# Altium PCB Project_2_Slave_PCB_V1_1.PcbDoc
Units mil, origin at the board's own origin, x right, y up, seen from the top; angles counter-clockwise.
Board outline 3444 x 3925 mil, 2 copper layers (Top Layer, Bottom Layer); 82 components, 95 nets, 252 pads, 68 vias.
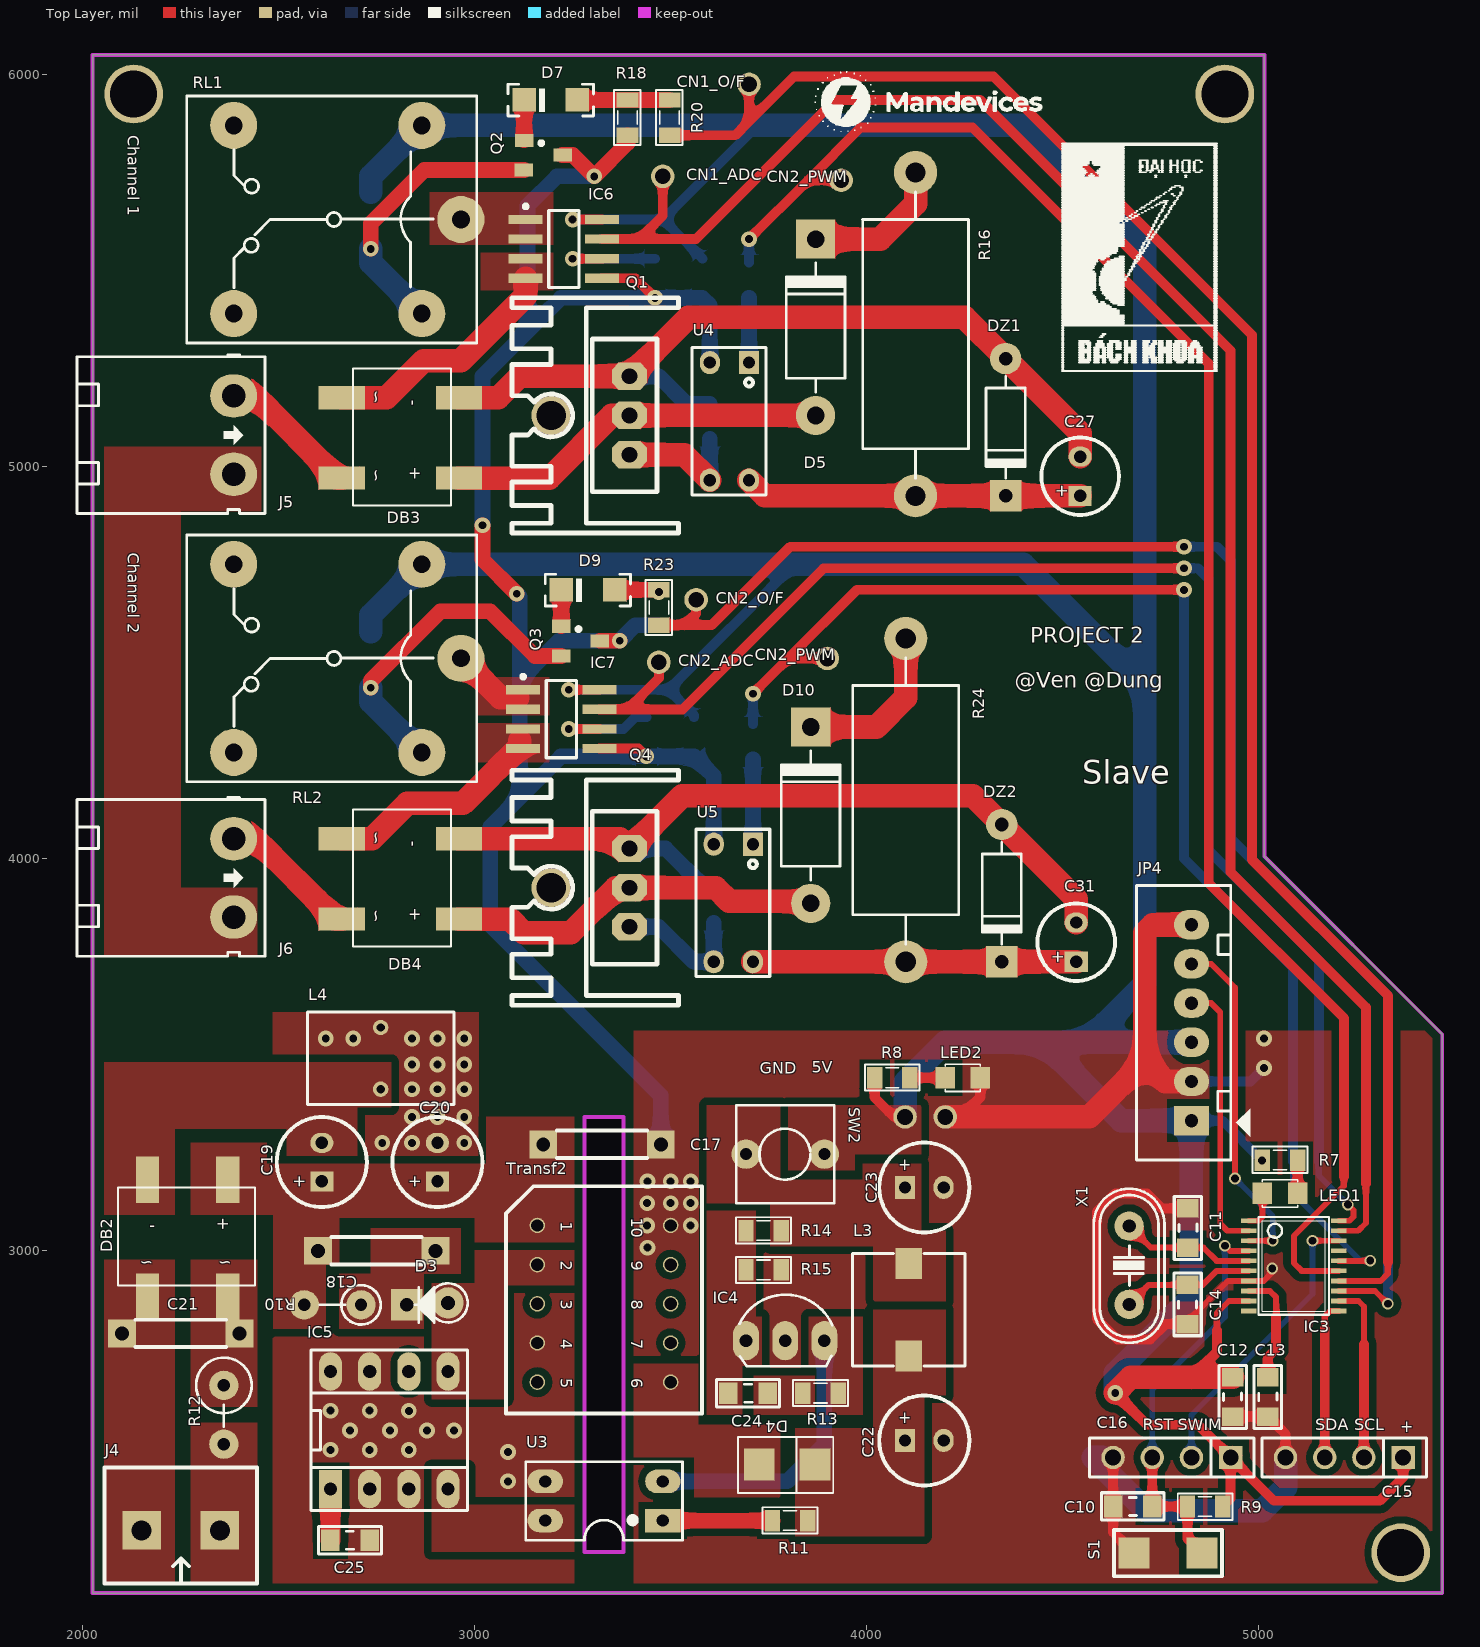
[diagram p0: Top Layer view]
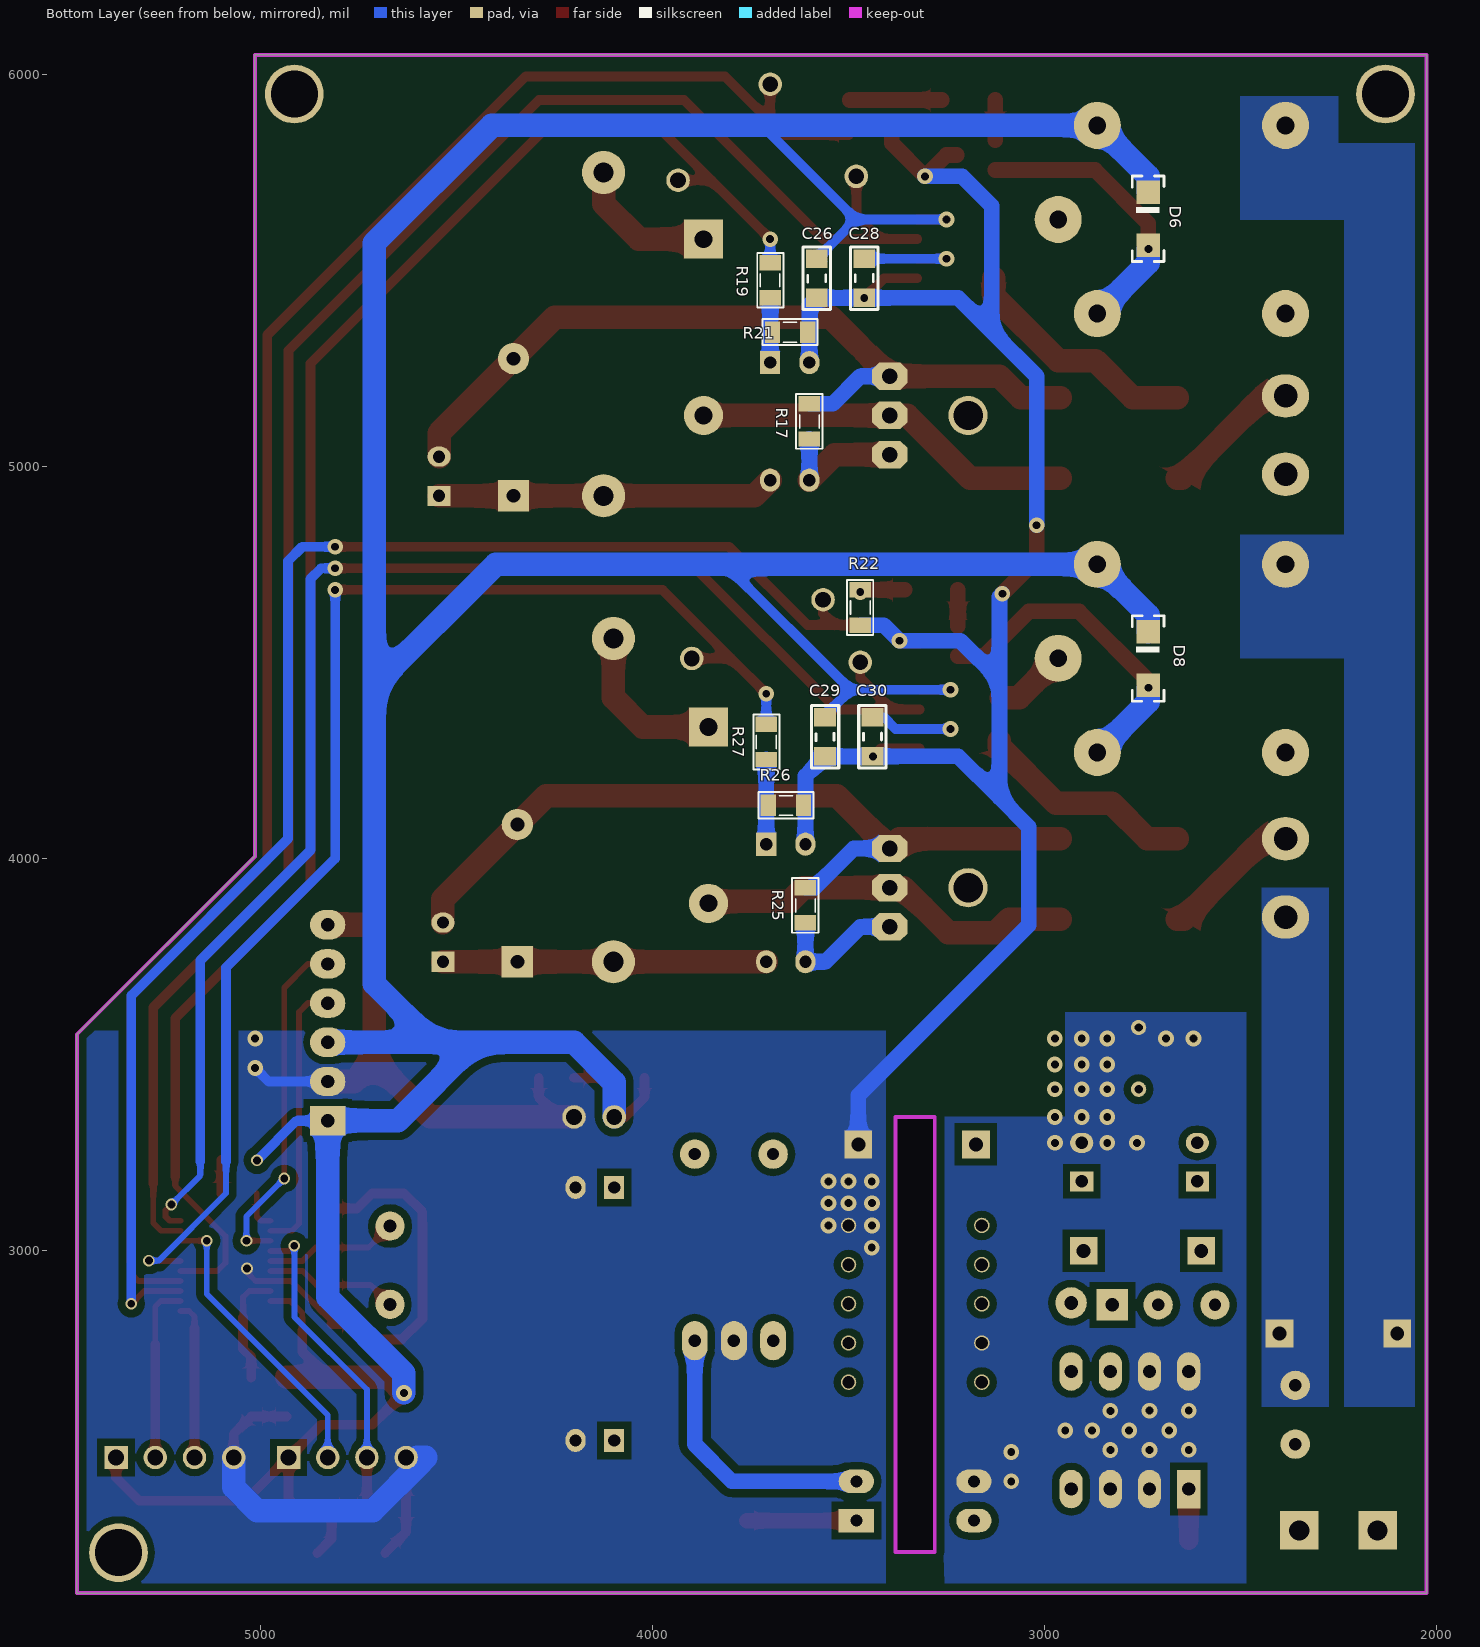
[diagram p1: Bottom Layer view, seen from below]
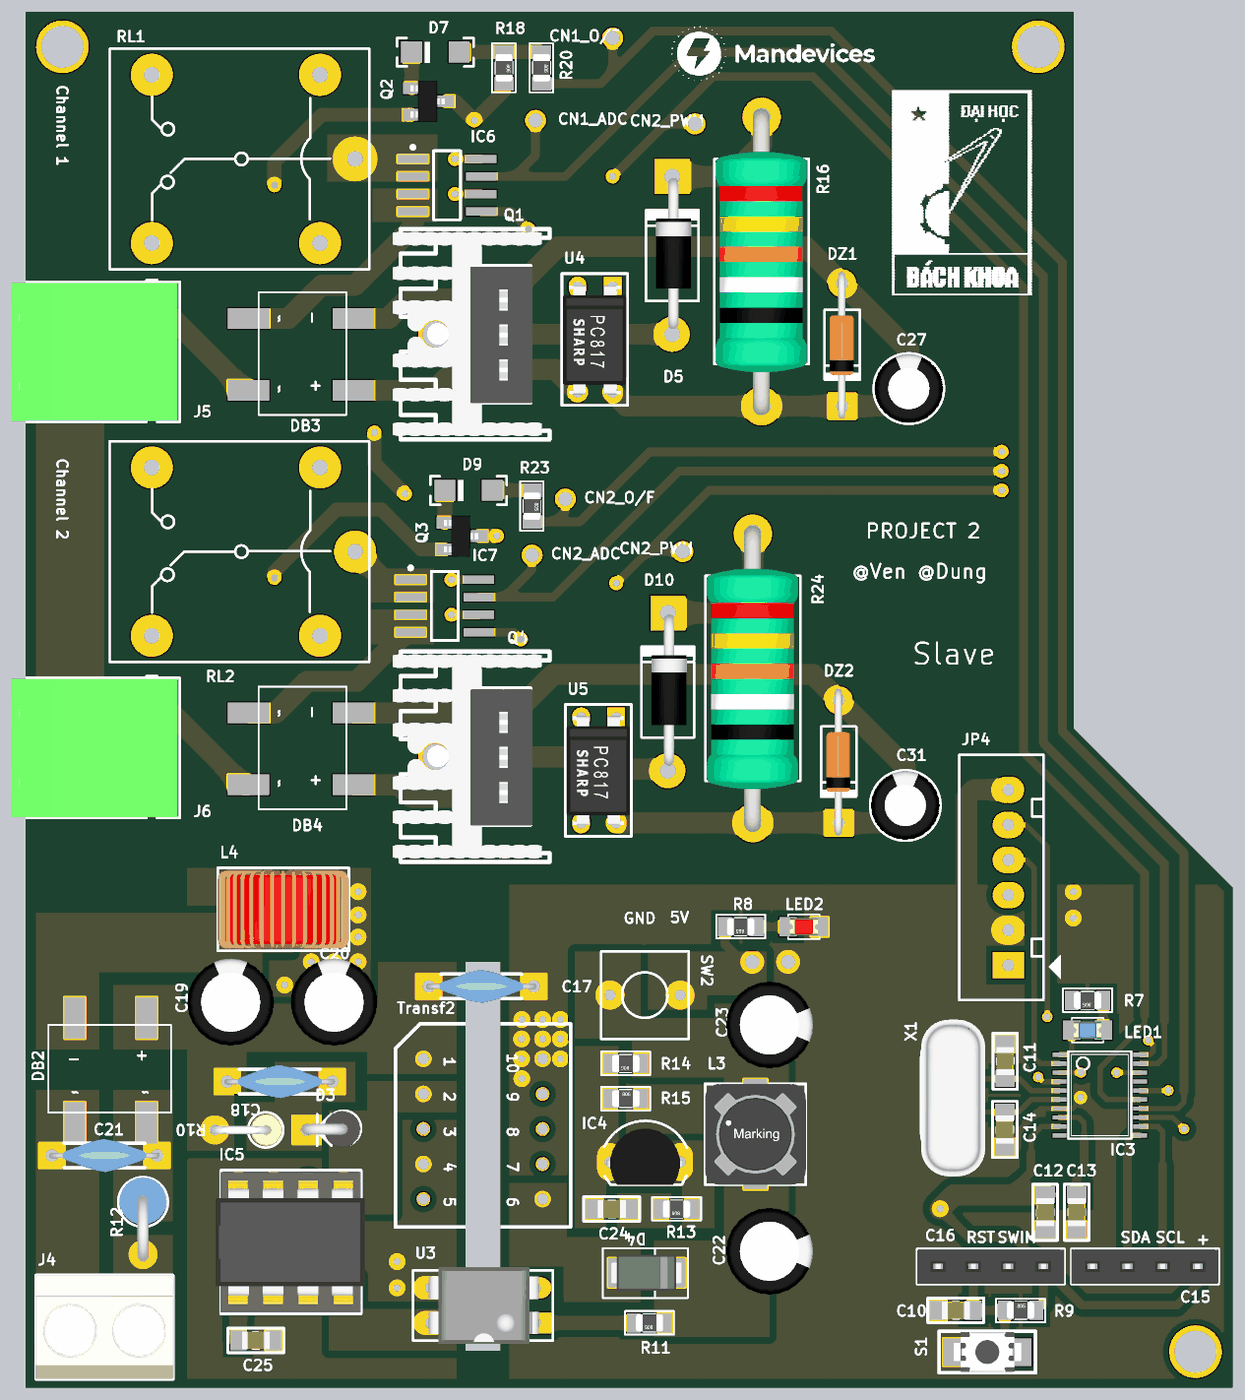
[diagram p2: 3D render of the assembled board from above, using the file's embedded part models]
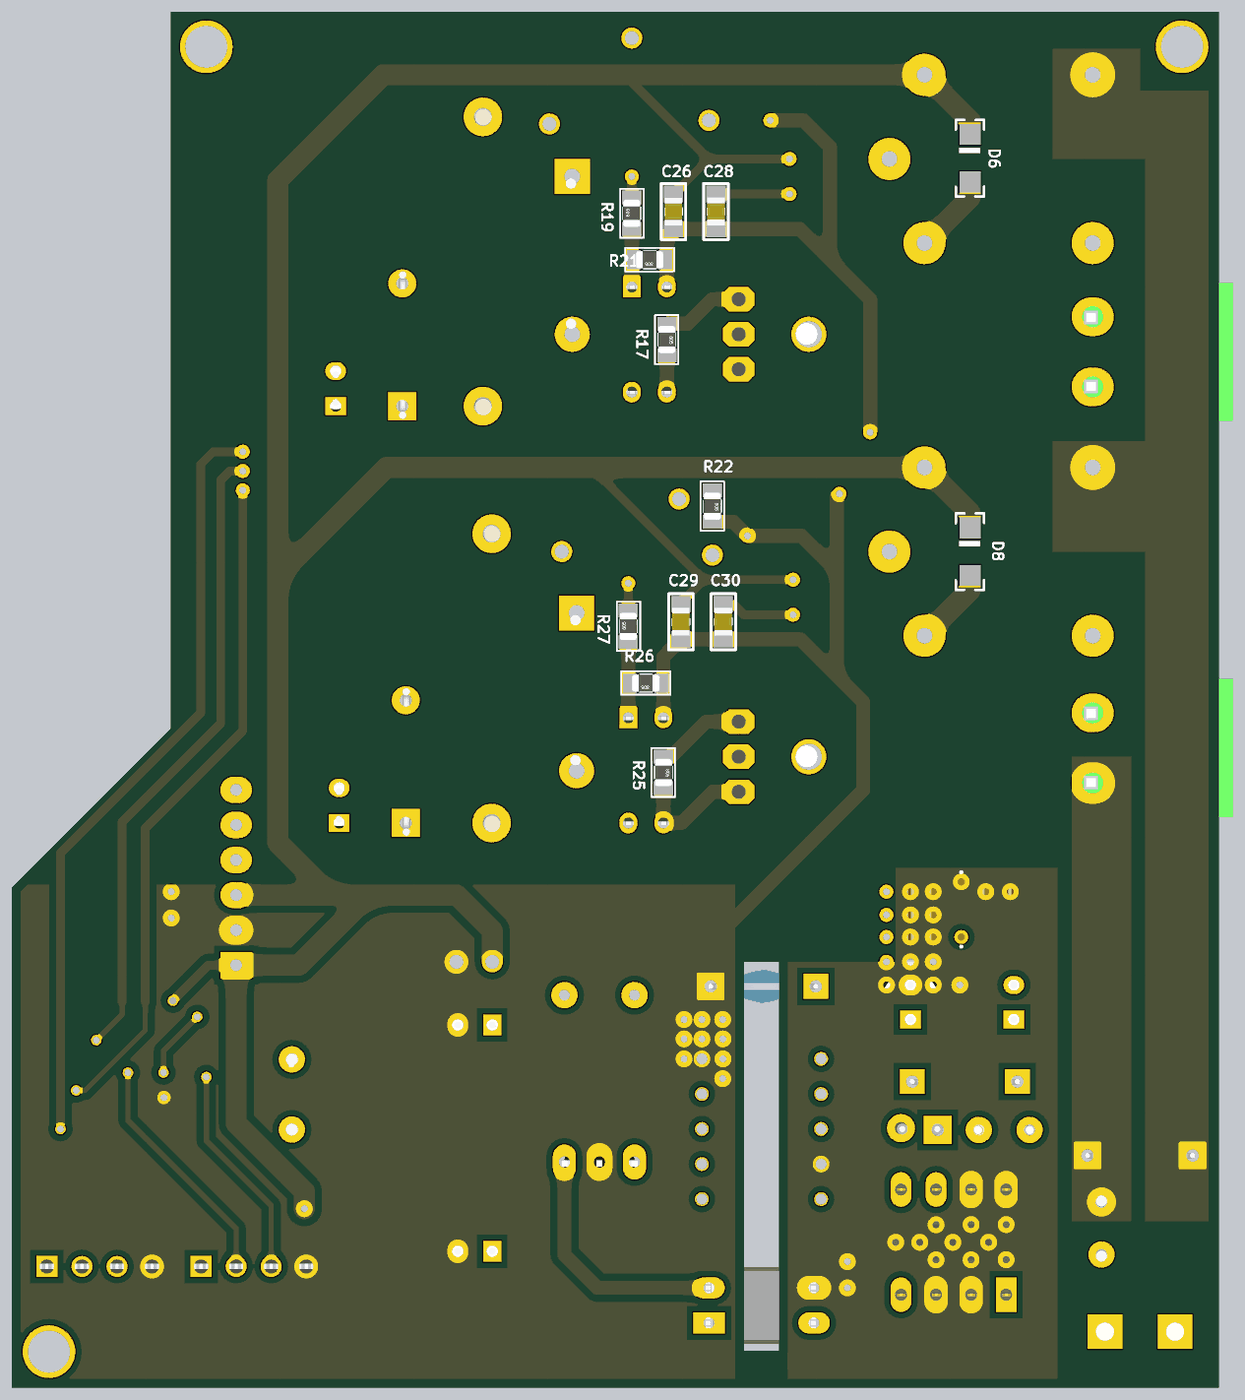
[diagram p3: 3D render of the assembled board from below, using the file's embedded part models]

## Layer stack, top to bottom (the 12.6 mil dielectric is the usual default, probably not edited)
Top Solder: solder mask 0.4, Solder Resist, Dk 3.5
Top Layer: signal copper 1.4
Dielectric 1: dielectric 12.6, FR-4, Dk 4.8
Bottom Layer: signal copper 1.4
Bottom Solder: solder mask 0.4, Solder Resist, Dk 3.5

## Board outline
2025,2125 2025,6050 5015,6050 5015,4005 5469,3551 5469,2125
cut-out: 3280,2230 3380,2230 3380,3340 3280,3340

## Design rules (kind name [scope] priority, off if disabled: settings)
Clearance [All] p1: gap=20 ignorepadtopadclearanceinfootprint=TRUE except(0: Arc-Text Arc-Hole Track-Text Track-Hole SMDPad-Text SMDPad-Hole THPad-Text THPad-Hole Via-Text Via-Hole Fill-Text Fill-Hole Poly-Text Poly-Hole Region-Text Region-Hole Text-Text Text-Hole; 10: Arc-Arc Arc-Track Arc-SMDPad Arc-THPad Arc-Via Track-Track Track-SMDPad Track-THPad Track-Via SMDPad-SMDPad SMDPad-THPad SMDPad-Via THPad-THPad THPad-Via Via-Via; 18: THPad-Fill THPad-Poly THPad-Region)
PolygonConnect [All] p1: connectstyle=Direct reliefconductorwidth=10 reliefentries=4 polygonreliefangle="90 Angle" airgapwidth=10
RoutingVias [All] p1: holewidth=20 width=40 viastyle="Through Hole" minholewidth=15 minwidth=25 maxholewidth=25 maxwidth=45
SolderMaskExpansion [All] p1: expansion=4
Width [All] p1: maxlimit=60 minlimit=15 preferedwidth=25
30 further rules are at their usual default settings.

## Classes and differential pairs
component class 8: JP4
component class 7: C26 C27 C28 C29 C30 C31 D5 D6 D7 D8 D9 D10 DB3 DB4 DZ1 DZ2 IC6 IC7 J5 J6 Q1 Q2 Q3 Q4 R16 R17 R19 R20 R23 R24 R25 R26 R27 RL1 RL2 U4 U5
component class 6: C17 C18 C19 C20 C21 C22 C23 C24 C25 D3 D4 DB2 IC4 IC5 J4 L3 R10 R11 R12 R13 R14 R15 SW2 Transf2 U3
component class 5: C10 C11 C12 C13 C14 C15 C16 IC3 LED1 LED2 R7 R8 R9 S1 X1

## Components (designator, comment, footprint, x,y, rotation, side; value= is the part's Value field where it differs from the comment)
C10 "1uF" CAP_0805 4679,2347 r0 top value=33p
C11 "22pF" CAP_0805 4819,3056.61 r90 top value=33p
C12 "100nF" CAP_0805 4933,2625.5 r90 top value=33p
C13 "1uF" CAP_0805 5023,2625.5 r90 top value=33p
C14 "22pF" CAP_0805 4820,2861.61 r270 top value=33p
C15 "JP4" JP4-C1T 5369,2471 r180 top
C16 "JP4" JP4-C1T 4929,2471 r180 top
C17 "1nF/400v" 103/2KV 3475.04,3270 r180 top
C18 "1nF/400V" 103/2KV 2600,2998.34 r0 top
C19 "6.8uF/400V" C8mm 2610,3224.71 r90 top
C20 "6.8uF/400V" C8mm 2905,3224.71 r90 top
C21 "20D471K" 103/2KV 2100,2787.5 r0 top
C22 "1000uF/16V" C8mm 4147.38,2514.45 r0 top
C23 "470uF/16V" C8mm 4147.38,3160 r0 top
C24 "100nF" CAP_0805 3697.38,2636 r0 top value=33p
C25 "100nF" CAP_0805 2681.99,2259 r180 top value=33p
C26 "100nF" CAP_0805 3580,5480 r270 bottom value=33p
C27 "Cap Pol" C5mm 4545,4975 r90 top
C28 "10nF" CAP_0805 3461,5480 r90 bottom value=33p
C29 "100nF" CAP_0805 3559,4310 r270 bottom value=33p
C30 "10nF" CAP_0805 3440,4310 r90 bottom value=33p
C31 "Cap Pol" C5mm 4535,3786 r90 top
D3 "1N4937" DIO-1AN 2876.99,2860.5 r0 top value=1N5007
D4 "SS14" DO-214AC(SMA) 3775,2450 r180 top value=1N5007
D5 "1N4007" D2A 3870,5580 r270 top
D6 "1N4148" 1N4148_SMD 2735,5632.09 r90 bottom value="Diode c?m 1N5408"
D7 "1N4148" 1N4148_SMD 3193.91,5935 r180 top value="Diode c?m 1N5408"
D8 "1N4148" 1N4148_SMD 2735,4510 r90 bottom value="Diode c?m 1N5408"
D9 "1N4148" 1N4148_SMD 3288.91,4685 r180 top value="Diode c?m 1N5408"
D10 "1N4007" D2A 3857.5,4335 r270 top
DB2 "Diode Bridge" DB207S 2270,3030 r0 top
DB3 "Diode Bridge Flate" DB207S 2810,5070 r270 top
DB4 "Diode Bridge Flate" DB207S 2810,3945 r270 top
DZ1 "Zener-12V" D1A 4355,5275 r90 top
DZ2 "Zener-12V" D1A 4345,4086 r90 top
IC3 "STM8S003F3P6" TSSOP-20 5090,2960 r270 top value=24Cxx
IC4 "TL431" qto-92 3792.38,2769 r0 top
IC5 "TNY264" DIP8 2780,2540.5 r90 top
IC6 "Current Sensor IC" SOIC-8 3227.44,5555 r0 top
IC7 "Current Sensor IC" SOIC-8 3221,4355 r0 top
J4 "AC-IN" KF2-5.08 2250,2285 r180 top
J5 "LOAD1" KF2-5.08T 2385,5180 r270 top
J6 "LOAD2" KF2-5.08T 2385,4050 r270 top
JP4 "Con6" CON6 4829,3330.42 r90 top value="Connector 6"
L3 "2.2uF" L-SMD-M-7.3x4.5 4107.38,2848.11 r180 top value="150 mH"
L4 "100uF" L-DIP-M-9.5x6 2760,3489.5 r90 top value="150 mH"
LED1 "LED" LED-0805-Blue 5100,3145 r180 top value="LED 3 ly Single Colour"
LED2 "LED" LED-0805-Red 4200.51,3440 r0 top value="LED 3 ly Single Colour"
Q1 "IRF840" QTO-220H3 3395,5030 r90 top
Q2 "2SC1815" SOT23 3175,5795 r270 top value=C1815
Q3 "2SC1815" SOT23 3270,4555 r270 top value=C1815
Q4 "IRF840" QTO-220H3 3395,3825 r90 top
R7 "1k" RES-SMD-0805 5055,3230 r180 top
R8 "1k" RES-SMD-0805 4065.51,3440 r180 top
R9 "10k" RES-SMD-0805 4864,2346 r0 top
R10 "200k" RES-1/4WD 2645,2860.5 r180 top
R11 "200R" RES-SMD-0805 3805,2310 r180 top
R12 "2R" RES-1WD 2360,2590 r270 top
R13 "3.3k" RES-SMD-0805 3882.37,2635 r180 top
R14 "10k" RES-SMD-0805 3737.37,3050 r180 top
R15 "10k" RES-SMD-0805 3737.38,2950 r0 top
R16 "56k/2W" RES-2W 4120,5345 r270 top value="R1/4W - 1K"
R17 "10k" RES-SMD-0805 3600,5115 r270 bottom value="R1/4W - 1K"
R18 "100k" RES-SMD-0805 3390,5890 r270 top
R19 "1k" RES-SMD-0805 3700,5475 r90 bottom
R20 "100R" RES-SMD-0805 3497.25,5890 r270 top
R21 "100k" RES-SMD-0805 3649,5342.31 r0 bottom
R22 "100k" RES-SMD-0805 3470,4640 r270 bottom
R23 "100R" RES-SMD-0805 3470,4640 r270 top
R24 "56k/2W" RES-2W 4095,4156 r270 top value="R1/4W - 1K"
R25 "10k" RES-SMD-0805 3610,3880 r270 bottom value="R1/4W - 1K"
R26 "100k" RES-SMD-0805 3660,4135 r0 bottom
R27 "1k" RES-SMD-0805 3710,4297 r90 bottom
RL1 "Relay 10A/12V" RL_SPDT_10A 2965,5630 r180 top value="Relay SPDT, 10A, 12V"
RL2 "Relay 10A/12V" RL_SPDT_10A 2965,4510 r180 top value="Relay SPDT, 10A, 12V"
S1 "SW-SMD" "SW 3x2x4" 4769,2227 r0 top
SW2 "SW" SW2 3692.38,3245 r0 top value="SW chip 2 pin"
Transf2 "Transformer EE16" "Transformer EE12.7" 3330,2863.18 r270 top
U3 "PC817" DIP4/W0.3 3480,2310 r90 top
U4 "OPTO" OPTO 3700,5264 r270 top value=TLP5211
U5 "OPTO" OPTO 3710,4035 r270 top value=TLP5211
X1 "8Mhz" XT2 4670,2961.61 r90 top value=4Mhz

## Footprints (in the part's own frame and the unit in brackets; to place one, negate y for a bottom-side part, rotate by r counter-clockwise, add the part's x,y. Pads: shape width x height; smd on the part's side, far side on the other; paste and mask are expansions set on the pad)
1N4148_SMD [mil]
  rect 60x60 smd: 1(-67.91,0) 2(67.91,0)
  silkscreen extent -109,-40 109,41, body extent -71,-23 67,25, height 47
103/2KV [mm]
  rect 1.8x1.8 hole 0.9: 1(0,0) 2(7.62,0)
  silkscreen extent 0.89,-0.89 6.73,0.89, body extent -0.19,-1.2 7.81,1.19, height 9.03
C5mm [mm]
  rect 1.3x1.5 hole 0.8: 1(-1.27,0)
  oval 1.3x1.5 hole 0.8: 2(1.27,0)
  silkscreen extent -2.51,-2.51 2.51,2.51, body extent -2.5,-2.5 2.49,2.5, height 11.01
C8mm [mm]
  rect 1.3x1.5 hole 0.8: 1(-1.25,0)
  oval 1.3x1.5 hole 0.8: 2(1.25,0)
  silkscreen extent -2.92,-2.92 2.92,2.92, body extent -3.15,-3.15 3.16,3.15, height 11.51
CAP_0805 [mm]
  rect 1.2x1.4 smd: 1(-1.27,-0.025) 2(1.27,-0.025)
  silkscreen extent -2.03,-0.91 2.03,0.86, body extent -1.01,-0.66 1.01,0.61, height 0.61
CON6 [mil] "CON6"
  rect 75x90 hole 34: 1(0,0)
  oval 75x90 hole 34: 2(100,0) 3(200,0) 4(300,0) 5(400,0) 6(500,0)
  silkscreen extent -100,-150 600,140
D1A [mil] "Diode 1A, W 100mil, L 350mil"
  round 80 hole 35: 1(0,0)
  rect 80x80 hole 35: 2(-350,0)
  silkscreen extent -305,-50 -45,50, body extent -386,-33 34,36, height 84
D2A [mil] "Diode 2A, W 150mil, L 450mil"
  round 100 hole 45: 1(450,0)
  rect 100x100 hole 45: 2(0,0)
  silkscreen extent 61,-75 391,75, body extent 5,-47 435,54, height 100
DB207S [mm] "Bridge Rectifiers 2A 1000V"
  rect 1.5x3 smd: 1(2.54,3.81) 2(2.54,-3.785) 3(-2.667,-3.785) 4(-2.667,3.81)
  silkscreen extent -4.57,-3.05 4.32,3.3
DIO-1AN [mil] "Diode 1A, W 100mil, L 150mil"
  round 80 hole 35: 1(55,5)
  rect 80x80 hole 35: 2(-50,0)
  silkscreen extent -30,-45 105,55, body extent -64,-50 104,55, height 252
DIP4/W0.3 [mil] "4 PIN, W 300mil, Pin to pin 100mil"
  rect 60x90 hole 31: 1(0,0)
  oval 60x90 hole 31: 2(100,0) 3(100,300) 4(0,300)
  silkscreen extent -50,-50 150,350, body extent -59,-10 159,305, height 170
DIP8 [mm]
  rect 2.5x1.5 hole 0.864: 1(-3.81,3.759)
  oval 2.5x1.5 hole 0.864: 2(-3.81,1.219) 3(-3.81,-1.321) 4(-3.81,-3.861) 5(3.81,-3.861) 6(3.81,-1.321) 7(3.81,1.219) 8(3.81,3.759)
  silkscreen extent -5.21,-5.13 5.21,5.03, body extent -5.08,-5.4 5.08,5.4, height 8.1
DO-214AC(SMA) [mm] "DO-214AC Diode Smallest Size"
  rect 2x2.1 smd: 1(1.245,-0.076) 2(-2.367,-0.076)
  silkscreen extent -3.56,-1.86 2.62,1.76, body extent -3.13,-1.38 2.07,1.22, height 2.4
JP4-C1T [mm] "4 row, straight, gold plating"
  rect 1.52x1.52 hole 1.02: 1(0,0)
  round 1.52 hole 1.02: 2(2.54,0) 3(5.08,0) 4(7.62,0)
  silkscreen extent -1.52,-1.27 9.14,1.27, body extent -1.52,-1.25 9.14,1.25, height 8.51
KF2-5.08 [mm]
  rect 2.5x2.5 hole 1.3: 1(-2.54,0) 2(2.54,0)
  silkscreen extent -4.95,-4.08 4.95,3.43, body extent -5,-4.07 5,3.43, height 10
KF2-5.08T [mil] "Header 2, 2 pin, hight 300mil, Pin to Pin 200, Colour Green"
  oval 110x120 hole 60: 1(0,0) 2(200,0)
  silkscreen extent -105,-400 300,80, body extent -97,-399 297,73, height 334
L-DIP-M-9.5x6 [mm] "Body 9.5x6mm, 2 leads"
  round 1 hole 0.55: 1(-2,0) 2(2,0)
  silkscreen extent -3,-4.75 3,4.75, body extent -2.85,-4.75 2.85,4.75, height 9.75
L-SMD-M-7.3x4.5 [mm] "WE-PDA SMD Shielded Power Inductor, 7345"
  rect 1.7x2 smd: 1(0,3) 2(0,-3)
  silkscreen extent -3.65,-3.65 3.65,3.65, body extent -3.65,-3.65 3.65,3.65, height 4.05
LED-0805-Blue [mil]
  rect 50x55 smd: 1(0,0) 2(90,0)
  silkscreen extent 0,-35 90,35, body extent 5,-25 85,25, height 43
LED-0805-Red [mil]
  rect 50x55 smd: 1(0,0) 2(90,0)
  silkscreen extent 0,-35 90,35, body extent 5,-25 85,25, height 43
OPTO [mm]
  rect 1.5x1.3 hole 0.8: 1(-0.025,0)
  oval 1.5x1.3 hole 0.8: 2(-0.025,-2.54) 3(7.595,-2.54) 4(7.595,0)
  silkscreen extent -0.99,-3.68 8.56,1.09, body extent -0.13,-3.59 7.75,1, height 4.81
qto-92 [mil] "TO-92"
  oval 66x100 hole 32: 1(-100,0) 2(0,0) 3(100,0)
  silkscreen extent -117,-65 120,118, body extent -109,-66 109,95, height 245
QTO-220H3 [mil] "TO-220 1-2-3"
  oct 70x90 hole 40: 1(0,0) 2(100,0) 3(200,0)
  round 100 hole 75: ""(100,200)
  silkscreen extent -200,-125 400,300, body extent -190,-102 392,323, height 984
RES-1/4WD [mil]
  round 75 hole 31.5: 1(-65,0) 2(80,0)
  silkscreen extent -115,-50 40,50, body extent -112,-45 92,46, height 379
RES-1WD [mil]
  round 75 hole 31.5: 1(-65,0) 2(85,0)
  silkscreen extent -136,-71 40,71, body extent -135,-67 105,67, height 498
RES-2W [mil] "R2W, 2 pin, 700mil"
  round 110 hole 51.18: 1(-405,5) 2(420,5)
  silkscreen extent -355,-130 375,140, body extent -428,-126 446,134, height 277
RES-SMD-0805 [mil]
  rect 39.37x55 smd: 1(-45,0) 2(45,0)
  silkscreen extent -70,-34 70,33, body extent -39,-25 39,25, height 31
RL_SPDT_10A [mil] "Relay SPDT, 5 pin, 10A,W 650mil, L 800mil, H 800mil"
  round 120 hole 45: 1(0,0) 2(580,240) 3(580,-240) 4(100,-240) 5(100,240)
  silkscreen extent -40,-315 700,315
SOIC-8 [mm] "SOIC, 8-Leads, Body 5,0x4,0mm (max), Pitch 1,27mm, IPC Medium Density"
  rect 2.2x0.6 smd: 1(-2.475,1.905) 2(-2.475,0.635) 3(-2.475,-0.635) 4(-2.475,-1.905) 5(2.475,-1.905) 6(2.475,-0.635) 7(2.475,0.635) 8(2.475,1.905)
  silkscreen extent -2.6,-2.5 0.98,2.88, body extent -3.2,-2.5 3.2,2.5, height 1.75
SOT23 [mm] "SOT 23 _ 1-3-2"
  rect 0.85x1.2 smd: 1(-0.94,-1.245) 2(0.985,-1.25) 3(0.005,1.25)
  silkscreen extent -0.88,-0.25 -0.64,0, body extent -1.47,-1.33 1.53,1.17, height 1.06
SW2 [mil] "SW button 2pin, 250x 250 mil"
  round 75 hole 31: 1(0,0) 2(200,0)
  silkscreen extent -25,-125 225,125
"SW 3x2x4" [mm]
  rect 2x2 smd: 1(-2.2,0) 2(2.2,0)
  silkscreen extent -3.5,-1.5 3.5,1.5, body extent -2.45,-1.45 2.45,1.45, height 2
"Transformer EE12.7" [mm]
  round 1 hole 0.8: 1(-5.08,-4.318) 2(-2.54,-4.318) 3(0,-4.318) 4(2.54,-4.318) 5(5.08,-4.318) 6(5.08,4.318) 7(2.54,4.318) 8(0,4.318) 9(-2.54,4.318) 10(-5.08,4.318)
  silkscreen extent -7.62,-6.35 7.11,6.35
TSSOP-20 [mil] "TSSOP-20"
  rect 12x39 smd: 1(-115.16,-114.87) 2(-89.57,-114.87) 3(-63.98,-114.87) 4(-38.39,-114.87) 5(-12.8,-114.87) 6(12.8,-114.87) 7(38.39,-114.87) 8(63.98,-114.87) 9(89.57,-114.87) 10(115.16,-114.87) 11(115.16,114.87) 12(89.57,114.87) 13(63.98,114.87) 14(38.39,114.87) 15(12.8,114.87) 16(-12.8,114.87) 17(-38.39,114.87) 18(-63.98,114.87) 19(-89.57,114.87) 20(-115.16,114.87)
  silkscreen extent -125,-90 125,90
XT2 [mil] "Footpin for Crystal 2 pin"
  round 75 hole 34: 1(-100,0) 2(100,0)
  silkscreen extent -198,-90 195,90, body extent -233,-93 213,90, height 138

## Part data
C10 C11 C12 C13 C14 C24 C25 C26 C28 C29 C30: library part CapSMD, "Capacitor"
C15 C16: "WR-PHD 2.54 mm Angled Socket Header", Manufacturer="Würth Elektronik eiSos GmbH", partNo=613004143121
C17 C18: library part Cap2KV, "CAP CERAMIC"
C19 C20 C22 C23: library part "Cap Pol", "Polarized Capacitor (Axial)"
C21: library part Cap2KV, "Varistor"
C27 C31: "Polarized Capacitor (Axial)"
D3: library part "Diode SMD", "Diode Schottky / 1N4937"
D4: library part "Diode SMD", "Diode Schottky / 1N5819"
D5 D10: library part D1A, "Diode 1A"
D6 D7 D8 D9: library part 1N5822, "Schottky Rectifiers"
DB2: library part "Diode Bridge Flate"
DB3 DB4: "Diode Bridge"
DZ1 DZ2: library part Zener
IC3: "MCU 8BIT  8KB FLASH TSSOP-20"
IC4: "Programmable Shunt Regulator"
IC5: "Enhanced, Energy Efficient, Low Power Off-line Switcher"
IC6 IC7: library part ACS712
J4 J5 J6: library part KF2, Manufacturer="W黵th Elektronik eiSos GmbH", partNo=691103110002
JP4: "PLC module"
L3 L4: library part L-DIP-1, "Inductor"
LED1 LED2: "LED Single colour Green and Red"
Q1 Q4: "MOSFET N - CHANNEL 500V - 0.75 - 8A - TO-220"
Q2 Q3: "NPN 600mW, ECB"
R7 R8 R9 R10 R11 R12 R13 R14 R15 R18 R19 R20 R21 R22 R23 R26 R27: library part "Resistor - SMD", "Resistor", Manufacturer="Generic Components"
R16 R17 R24 R25: library part "Resistor - DIP", "Resistor - DIP"
RL1 RL2: library part "Relay 1", "Relay SPDT,10A - 12VDC 5 Pin"
S1: "Switch"
SW2: library part SW2, "Switch button 2 pin"
Transf2: library part "Tranformer EE16"
U3 U4 U5: "Single Opto"
X1: library part XT2, "Crystal For all Crystal 2pin."

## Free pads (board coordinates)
  round 150 hole 120: 0(2130,5950) 0(4914.23,5950) 0(5363,2228)
  round 60 hole 40: 4(3480,5740) 5(3470,4500) 6(4098.16,3340) 6(4200.51,3340) 7(3900,4510) 8(3565,4660) 9(3700,5975) 10(3935,5730)

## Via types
v1: diameter 40, hole 20, Top Layer to Bottom Layer, 59 vias
v2: diameter 30, hole 20, Top Layer to Bottom Layer, 9 vias

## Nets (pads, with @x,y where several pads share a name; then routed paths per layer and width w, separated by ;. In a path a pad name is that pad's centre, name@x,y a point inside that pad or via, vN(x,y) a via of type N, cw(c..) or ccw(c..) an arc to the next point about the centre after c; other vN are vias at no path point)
3.3V: 
5V: C12.2 C15.1 C16.1 C26.1 C29.1 D6.2 D8.2 IC3.9 IC6.8 IC7.8 JP4.1 JP4.3 pad.6@4098.16,3340 R7.2 R8.2 R9.2 RL1.4 RL2.4 SW2.2 | length 12291.1
  Top Layer w15: 4893.91,2795 4893.91,2839.68 4924.67,2870.43 IC3.9
  Top Layer w25: v1(3240,4430) IC7.8 ; v1(3250,5630) IC6.8 ; R8.2 4020.51,3390 4070.51,3340 pad.6@4098.16,3340 ; v1(4634.43,2635.75) 4715.71,2554.47 4845.53,2554.47 C16.1 ; 4829,2675.5 4893.91,2740.41 4893.91,2795 ; R9.2 4929,2366 C16.1 ; C15.1 5369,2419.93 5309.45,2360.38 5039.62,2360.38 C16.1
  Top Layer w60: v1(4634.43,2635.75) 4674.19,2675.5 4829,2675.5 C12.2
  Bottom Layer w25: v1(3240,4430) 3495,4430 ; v1(3250,5630) 3481,5630 ; C29.1 3560,4365 3495,4430 ; C26.1 3481,5630 ; 3720,5870 3720,5869 3481,5630 ; 3815,4750 3495,4430 ; JP4.1 4908.18,3330.42 v2(5009.4,3229.2)
  Bottom Layer w60: D8.2 2735,4620 RL2.4 3815,4750 4400,4750 4710,4440 ; D6.2 2735,5740 RL1.4 3720,5870 4410,5870 4710,5570 4710,4440 ; pad.6@4098.16,3340 4098.16,3428.16 4200.42,3530.42 4450,3530.42 ; v1(4634.43,2635.75) 4634.43,2685.45 4829,2880.02 JP4.1 4650,3330.42 4450,3530.42 ; JP4.3 4560.42,3530.42 ; 4450,3530.42 4560.42,3530.42 ; 4560.42,3530.42 4710,3680 4710,4440
AC1: C21.2 DB2.2 J5.2 J6.2 R12.1
AC2: C21.1 DB2.3 J4.2 RL1.3 RL2.3
CS: 
DC: 
GND: C10.1 C11.2 C12.1 C13.1 C14.2 C15.4 C16.4 C17.1 C22.2 C23.2 C26.2 C28.1 C29.2 C30.1 IC3.7 IC4.2 IC6.5 IC7.5 JP4.2 JP4.6 LED2.2 pad.6@4200.51,3340 Q2.3 Q3.3 R15.2 R18.2 R21.1 R22.2 R26.1 S1.1 Transf2.10 U4.2 U5.2 | length 9042.4
  Top Layer w15: C14.2 4819,2818.79 4921.83,2921.61 IC3.7 5013.42,2921.61 5035,2943.2 v2(5035,2952.98)
  Top Layer w25: IC7.5 3418,4280 v1(3438,4260) ; IC6.5 3410,5480 v1(3460,5430) ; v1@3369.8,4554.8 v1(3370,4555) ; C22.2@4207.38,2514.45 C22.2@4207.38,2526.38 ; 4240.51,3340 4290.51,3390 LED2.2 ; C16.4 C10.1 4629,2280.39 S1.1 ; C14.2 4763.49,2811.61 4723.61,2771.74 4640.36,2771.74 4587.26,2824.84 4587.26,3069.96 4587.69,3070.4 4587.69,3098.26 4634.43,3145 4715.71,3145 4754.1,3106.61 C11.2 ; C12.1 C13.1 5069,2530.5 C15.4
  Top Layer w40: v1(3020,4850) 3020,4762.5 v1(3107.5,4675) ; Q2.3 3250.2,5794.8 v1(3305,5740) 3390,5825 R18.2 ; Q3.3 v1@3369.8,4554.8
  Top Layer w60: pad.6@4200.51,3340 4240.51,3340 4567.99,3340 4710,3482.01 ; JP4.2 4761.59,3430.42 4710,3482.01 ; JP4.6 4730.42,3830.42 4710,3810 4710,3482.01
  Bottom Layer w25: 4589.6,2459.85 4600.75,2471 C16.4 ; JP4.2 4979.65,3430.42 v1(5014.23,3465)
  Bottom Layer w40: v1(3020,4850) 3020,5230 3135,5345 ; v1(3107.5,4675) 3115,4667.5 3115,4455 ; v1(3305,5740) 3210,5740 3135,5665 3135,5345 ; R22.2 3410,4595 v1(3370,4555) 3215,4555 3115,4455 ; C17.1 3475.04,3394.96 3040,3830 3040,4080 3115,4155 ; U4.2 3600,5411 C26.2 v1(3460,5430) 3220,5430 3135,5345 ; U5.2 3610,4210 C29.2 C30.1 v1(3438,4260) 3220,4260 3115,4155 ; 3115,4155 3115,4455
  Bottom Layer w60: 4578.45,2471 C16.4@4600.75,2471 ; 4589.6,2459.85 4714.2,2335.25 5009.25,2335.25 5069,2395 C15.4
  other v1: 3440.79,3006.61 3440,3063.18 3551.11,3063.18 3440,3120 3500,3120 3551.11,3120 3440.79,3175.5 3500,3175.5 3551.11,3175.5 5014.23,3540
GND1: C27.2 DB3.4 DZ1.1 Q1.3 R17.1 | length 2086.1
  Top Layer w60: DB3.4 3060,5175 3115,5230 Q1.3 3545,5380 4250,5380 DZ1.1 4545,5085 C27.2
  Bottom Layer w40: Q1.3 3470,5230 3540,5160 R17.1
GND2: C31.2 DB4.4 DZ2.1 Q4.3 R25.1 | length 2067
  Top Layer w60: DB4.4 3370,4050 Q4.3 3530,4160 4271,4160 DZ2.1 4535,3896 C31.2
  Bottom Layer w40: Q4.3 3487,4025 3587,3925 R25.1
GND_IN: C20.2 C25.1 IC5.2 IC5.3 IC5.7 IC5.8 L4.2 Transf2.4 U3.3
  other v1: 3085,2410 3085,2484.84 2631.99,2490.5 2731.99,2490 2831.99,2490 2682.01,2540 2784.06,2540 2878.49,2540 2947.01,2540 2631.99,2590.5 2731.99,2590.5 2831.99,2590 2764.07,3273.93 2840,3273.93 2973.2,3273.93 2840,3340 2905,3340 2973.51,3340 2840,3410.76 2904.99,3410.76 2973.51,3410.64 2840,3473.81 2904.99,3473.81 2973.51,3473.84 2620,3540 2690,3540 2840,3540 2904.99,3540 2973.51,3540
I1_IN: IC6.1 IC6.2 RL1.1
I1_OUT: DB3.3 IC6.3 IC6.4 | length 621.7
  Top Layer w60: DB3.3 2775,5175 2870,5270 2965,5270 3130,5435 IC6.4
I2_IN: IC7.1 IC7.2 RL2.1 | length 186.4
  Top Layer w60: RL2.1 3065,4410 3110,4410
I2_OUT: DB4.3 IC7.3 IC7.4 | length 566.3
  Top Layer w60: DB4.3 2738,4050 2828,4140 2970,4140 3115,4285 3115,4300
LED: 
MOSI: 
NetC1_2: 
NetC2_2: 
NetC3_2: 
NetC5_1: 
NetC5_2: 
NetC6_1: 
NetC7_1: 
NetC8_1: 
NetC8_2: 
NetC9_2: 
NetC13_2: C13.2 IC3.8 | length 289.8
  Top Layer w15: IC3.8 5029.11,2896.02 5045,2880.14 5045,2827.88
  Top Layer w25: C13.2 5024,2727.29 5045,2748.29 5045,2827.88
NetC17_2: C17.2 C18.1 C19.1 C20.1 DB2.1 R10.2 Transf2.1
NetC18_2: C18.2 D3.2 R10.1
NetC19_2: C19.2 DB2.4 L4.1
NetC22_1: C22.1 D4.2 L3.1 R11.1
NetC23_1: C23.1 L3.2 R14.1 SW2.1
NetC24_1: C24.1 IC4.1 R14.2 R15.1
NetC24_2: C24.2 R13.2
NetC25_2: C25.2 IC5.1 | length 130.5
  Top Layer w50: C25.2 IC5.1
NetC27_1: C27.1 DZ1.2 R16.2 U4.4 | length 861.6
  Top Layer w60: U4.4 3740,4925 R16.2 DZ1.2 C27.1
NetC28_2: C28.2 IC6.6 | length 284.9
  Top Layer w25: v1(3250,5530) IC6.6
  Bottom Layer w25: v1(3250,5530) C28.2
NetC30_2: C30.2 IC7.6 | length 289.9
  Top Layer w25: v1(3240,4330) IC7.6
  Bottom Layer w25: v1(3240,4330) 3380,4330 3410,4360 C30.2
NetC31_1: C31.1 DZ2.2 R24.2 U5.4 | length 825
  Top Layer w60: U5.4 R24.2 DZ2.2 C31.1
NetD1_1: 
NetD2_1: 
NetD3_1: D3.1 IC5.5 Transf2.2
NetD4_1: D4.1 Transf2.6
NetD5_1: D5.1 DB3.1 Q1.2 | length 976.3
  Top Layer w60: DB3.1 3190,4970 3350,5130 Q1.2 D5.1
NetD5_2: D5.2 R16.1 | length 372.3
  Top Layer w60: D5.2 4035,5580 4125,5670 R16.1
NetD6_1: D6.1 Q2.2 RL1.5 | length 731.1
  Top Layer w40: v1(2735,5555) 2735,5620 2871.2,5756.2 Q2.2
  Bottom Layer w60: v1(2735,5555) 2735,5520 RL1.5
NetD7_1: D7.1 R18.1 R20.1 | length 235.4
  Top Layer w40: D7.1 R18.1 R20.1
NetD7_2: D7.2 Q2.1 | length 103
  Top Layer w40: Q2.1 D7.2
NetD8_1: D8.1 Q3.2 RL2.5 | length 843.1
  Top Layer w40: v1(2735,4435) 2735,4453 2912,4630 3040,4630 3153.8,4516.2 Q3.2
  Bottom Layer w60: v1(2735,4435) 2735,4400 RL2.5
NetD9_1: D9.1 R22.1 R23.1 | length 113.2
  Top Layer w40: D9.1 R23.1
  other v1: 3470.01,4679.36
NetD9_2: D9.2 Q3.1 | length 93
  Top Layer w40: Q3.1 D9.2
NetD10_1: D10.1 DB4.1 Q4.2 | length 976.2
  Top Layer w60: DB4.1 3090,3845 3125,3810 3245,3810 3360,3925 Q4.2 3615,3925 3650,3890 3852.5,3890 D10.1
NetD10_2: D10.2 R24.1 | length 424.6
  Top Layer w60: D10.2 4025,4335 4100,4410 R24.1
NetDB3_2: DB3.2 J5.1 | length 363
  Top Layer w60: J5.1 2440,5180 2650,4970 DB3.2
NetDB4_2: DB4.2 J6.1 | length 360.9
  Top Layer w60: J6.1 2440,4050 2645,3845 DB4.2
NetIC1_3: 
NetIC2_4: 
NetIC3_1: IC3.1 LED1.2 | length 98.8
  Top Layer w15: IC3.1 4999.92,3075.16 5010,3085.24 LED1.2
NetIC3_13: IC3.13 pad.8 R23.2 | length 3835.7
  Top Layer w15: IC3.13 5297.32,2896.02 v2(5330.16,2863.18)
  Top Layer w25: R23.2 3535,4595 ; pad.8 3565,4625 3535,4595 ; v1(4810,4795) 3805,4795 3605,4595 3535,4595
  Bottom Layer w25: v1(4810,4795) 4894.04,4795 4930.06,4758.98 4930.06,4049.95 5330.16,3649.85 v2(5330.16,2863.18)
NetIC3_14: IC3.14 pad.9 R20.2 | length 4585.8
  Top Layer w15: IC3.14 5311.83,2921.61 5330.21,2940 5330.21,2969.36
  Top Layer w25: R20.2@3500,5845 3665,5845 3700,5880 ; pad.9 3700,5880 ; 5330.21,2969.36 5330.21,3649.35 4983.28,3996.29 4983.28,5335.57 4323.85,5995 3815,5995 3700,5880
NetIC3_15: IC3.15 pad.10 R19.2 | length 4299.5
  Top Layer w15: IC3.15 5110.19,2947.2 5090.25,2967.14 5090.25,3036.32 5217.9,3163.97 5217.9,3187.25
  Top Layer w25: v1(3700,5580) 3850,5730 ; pad.10 3850,5730 ; 5217.9,3187.25 5217.9,3592.01 4872.93,3936.98 4872.93,5262.45 4270.38,5865 3985,5865 3850,5730
  Bottom Layer w25: R19.2 v1(3700,5580)
NetIC3_16: IC3.16 pad.7 R27.2 | length 3391.9
  Top Layer w15: IC3.16 5284.91,2972.8 v2(5285.44,2973.32)
  Top Layer w25: v1(3710,4420) 3800,4510 ; pad.7 3800,4510 ; v1(4810,4685) 3975,4685 3800,4510
  Bottom Layer w15: 5088.44,3226.2 5088.44,3145.19 5260.31,2973.32 v2(5285.44,2973.32)
  Bottom Layer w25: R27.2 v1(3710,4420) ; v1(4810,4685) 4810,3999.75 5088.44,3721.31 5088.44,3226.2
NetIC3_19: IC3.19 IC6.7 pad.4 | length 4647.9
  Top Layer w15: IC3.19 5254.45,3049.57 5274.29,3069.41 5274.29,3170
  Top Layer w25: IC6.7 3420,5580 ; pad.4 3480,5640 3420,5580 ; 5274.29,3170 5274.29,3619.71 4929,3965 4929,5296 4290,5935 3920,5935 3565,5580 3420,5580
NetIC3_20: IC3.20 IC7.7 pad.5 | length 3690.8
  Top Layer w15: IC3.20 5232.4,3075.16 5242.58,3085.33 5242.58,3101.86 v2(5228.03,3116.4)
  Top Layer w25: IC7.7 3390,4380 ; pad.5 3470,4460 3390,4380 ; v1(4810,4740) 3890,4740 3530,4380 3390,4380
  Bottom Layer w15: 5154.22,3226.06 5154.22,3190.21 v2(5228.03,3116.4)
  Bottom Layer w25: v1(4810,4740) 4846.31,4740 4873,4713.31 4873,4020.54 5154.22,3739.31 5154.22,3226.06
NetIC4_3: IC4.3 R13.1 U3.2 | length 715.7
  Bottom Layer w40: U3.2 3797.38,2410 3892.38,2505 IC4.3
NetIC5_4: IC5.4 U3.4
NetJ3_2: 
NetJ4_1: J4.1 R12.2
NetJP3_4: 
NetJP3_5: 
NetLED1_1: LED1.1 R7.1 | length 85
  Top Layer w25: LED1.1 R7.1
NetLED2_1: LED2.1 R8.1 | length 90
  Top Layer w25: R8.1 LED2.1
NetQ1_1: Q1.1 R17.2 U4.3 | length 336.9
  Top Layer w60: Q1.1 3535,5030 U4.3
  Bottom Layer w40: U4.3 R17.2
NetQ4_1: Q4.1 R25.2 U5.3 | length 350.9
  Bottom Layer w40: Q4.1 3470,3825 3559,3736 U5.3 R25.2
NetR2_2: 
NetR11_2: R11.2 U3.1 | length 280
  Top Layer w40: U3.1 R11.2
NetR19_1: R19.1 R21.2 U4.1 | length 165
  Bottom Layer w40: U4.1 R19.1
NetR26_2: R26.2 R27.1 U5.1 | length 216
  Bottom Layer w40: U5.1 R27.1
OSC1: C11.1 IC3.5 X1.2 | length 341.9
  Top Layer w15: X1.2 4725,3006.61 C11.1 4859.46,3006.61 4893.28,2972.8 IC3.5
OSC2: C14.1 IC3.6 X1.1 | length 340.6
  Top Layer w15: X1.1 4720,2911.61 C14.1 4857.69,2911.61 4893.28,2947.2 IC3.6
RS: 
RST: C10.2 C16.3 IC3.4 R9.1 S1.2 | length 1032.7
  Top Layer w15: v2(4914.23,3011.47) 4927.32,2998.39 IC3.4
  Top Layer w25: C16.3 C10.2 R9.1 4819,2263.62 S1.2
  Bottom Layer w15: C16.3 4729,2644.27 4914.23,2829.5 v2(4914.23,3011.47)
RX2: 
SCK: 
SCL: 
SDA: 
STM8_RX: IC3.3 JP4.5 | length 883.1
  Top Layer w15: JP4.5 4879.58,3730.42 4940,3670 v2(4940,3182.8) ; IC3.3 5036.14,3023.98 v2(5036.39,3024.23)
  Bottom Layer w15: v2(4940,3182.8) 5036.39,3086.41 v2(5036.39,3024.23)
STM8_SCL: C15.2 IC3.12 | length 455.6
  Top Layer w15: IC3.12 5255.17,2870.43 5269.15,2856.45 5269.15,2760 5269,2759.85
  Top Layer w25: C15.2 5269,2759.85
STM8_SDA: C15.3 IC3.11 | length 401.6
  Top Layer w15: 5169,2800 5169,2831.06 5182.78,2844.84 IC3.11
  Top Layer w25: C15.3 5169,2800
STM8_SWIM: C16.2 IC3.18 | length 747.9
  Top Layer w15: v2(5137.82,3023.87) 5137.92,3023.98 IC3.18
  Bottom Layer w15: C16.2 4829,2579.52 5137.82,2888.34 v2(5137.82,3023.87)
STM8_TX: IC3.2 JP4.4 | length 703.1
  Top Layer w15: JP4.4 4879.58,3630.42 4902.5,3607.5 4902.5,3067.43 4920.36,3049.57 IC3.2
T_CS: 
T_DO: 
T_IQR: 
TX2: 
pads on no net: IC3.10 IC3.17 IC5.6 Q1. Q4. RL1.2 RL2.2 Transf2.3 Transf2.5 Transf2.7 Transf2.8 Transf2.9

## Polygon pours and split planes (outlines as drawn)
GND on Top Layer "GND_L01_P144" (solid, remove dead copper, pour order 144): 3405.49,2125 3405.49,3560 5460,3560 5469,3551 5469,2125
GND_IN on Top Layer "GND_IN_L01_P140" (solid, remove dead copper, pour order 140): 2485,3607.61 3010,3607.61 3010,3340 3254.51,3340 3254.51,2125 2485,2125
NetD3_1 on Top Layer "NETD3_1_L01_P138" (solid, remove dead copper, pour order 138): 3280,3000 3000,3000 3000,2916 2999.5,2915.5 2890.5,2915.5 2890.5,2620 3080,2620 3080,2910 3280,2910
NetC19_2 on Top Layer "NETC19_2_L01_P136" (solid, remove dead copper, pour order 136): 2235,3090 2055,3090 2055,3480 2786.88,3480 2786.88,3365 2700,3365 2700,3240 2520,3240 2520,3310 2235,3310
NetC17_2 on Top Layer "NETC17_2_L01_P134" (solid, remove dead copper, pour order 134): 2580,3083.18 3000,3083.18 3000,3020 3280,3020 3280,3340 3030,3340 3030,3235.99 3029.01,3235 3029.01,3220 2580,3220
NetC17_2 on Top Layer "NETC17_2_L01_P132" (solid, remove dead copper, pour order 132): 2620,2800 2620,2963.34 2655,2963.34 2655,3220 2470,3220 2470,3273.93 2275,3273.93 2275,3090 2485.98,3090 2485.98,2800
NetC18_2 on Top Layer "NETC18_2_L01_P130" (solid, remove dead copper, pour order 130): 2655,2800 2655,2940 2735,2940 2735,3055.35 2965,3055.35 2965,2940 2870,2940 2870,2800
NetIC5_4 on Top Layer "NETIC5_4_L01_P128" (solid, remove dead copper, pour order 128): 2890,2445.5 2981.99,2445.5 2981.99,2350 3280,2350 3280,2230 2890,2230
5V on Top Layer "5V_L01_P126" (solid, remove dead copper, pour order 126): 3970,3204 3800,3204 3800,3370 4140,3370 4140,3245 3970,3245
NetC23_1 on Top Layer "NETC23_1_L01_P124" (solid, remove dead copper, pour order 124): 3592.38,3120 3592.38,3370 3780,3370 3780,3180 4000,3180 4000,3080 3995,3075 3754.38,3075 3754.38,3120
NetC23_1 on Top Layer "NETC23_1_L01_P122" (solid, remove dead copper, pour order 122): 4017.09,2869.61 4202.38,2869.61 4202.38,3049.57 4201.95,3049.99 4140,3049.99 4140,3220 3990,3220 3990,3100.7 3754.38,3100.7 3754.38,3010 4017.38,3010
NetC23_1 on Top Layer "NETC23_1_L01_P120" (solid, remove dead copper, pour order 120): 4202.38,2888.34
NetD4_1 on Top Layer "NETD4_1_L01_P118" (solid, remove dead copper, pour order 118): 3380,2710 3570,2710 3570,2555 3780,2555 3780,2368.87 3560.3,2369.13 3559.96,2471 3380,2471
I1_IN on Top Layer "I1_IN_L01_P116" (solid, remove dead copper, pour order 116): 3200,5565 2885,5565 2885,5700 3200,5700
I1_OUT on Top Layer "I1_OUT_L01_P114" (solid, remove dead copper, pour order 114): 3015,5450 3200,5450 3200,5545 3015,5545
I2_IN on Top Layer "I2_IN_L01_P106" (solid, remove dead copper, pour order 106): 3005,4365 3190,4365 3190,4462 3005,4462
AC1 on Top Layer "AC1_L01_P112" (solid, remove dead copper, pour order 112): 2445,3750 2055,3750 2055,5050 2456,5050 2456,4885 2250,4885 2250,3925 2445,3925
I2_IN on Top Layer "I2_IN_L01_P104" (solid, remove dead copper, pour order 104): 2995,4259
I2_OUT on Top Layer "I2_OUT_L01_P102" (solid, remove dead copper, pour order 102): 3190,4345 3190,4245 3005,4245 3005,4345
GND on Top Layer "GND_L01_P082" (solid, remove dead copper, pour order 82): 3752.38,2705 3752.38,2990 3832.38,2990 3832.38,2705
NetC24_1 on Top Layer "NETC24_1_L01_P080" (solid, remove dead copper, pour order 80): 3717.38,2825 3717.38,3100 3592.38,3100 3592.38,2825
NetC24_1 on Top Layer "NETC24_1_L01_P078" (solid, remove dead copper, pour order 78): 3682.38,2580 3592.38,2580 3592.38,2830 3732.38,2830 3732.38,2705 3682.38,2705
NetC24_2 on Top Layer "NETC24_2_L01_P076" (solid, remove dead copper, pour order 76): 3867.38,2680 3867.38,2580 3712.38,2580 3712.38,2680
NetIC4_3 on Top Layer "NETIC4_3_L01_P072" (solid, remove dead copper, pour order 72): 3852.38,2830 3990,2830 3990,2580 3897.38,2580 3897.38,2705 3852.38,2705
NetC22_1 on Top Layer "NETC22_1_L01_P064" (solid, remove dead copper, pour order 64): 4017.13,2630 4202.38,2630 4202.38,2848.11 4017.66,2848.11
NetC22_1 on Top Layer "NETC22_1_L01_P060" (solid, remove dead copper, pour order 60): 4017.38,2580 4017.38,2830 4147.38,2830 4147.38,2580
NetC22_1 on Top Layer "NETC22_1_L01_P056" (solid, remove dead copper, pour order 56): 3817.38,2270 3817.38,2545 4017.38,2545 4017.38,2580 4147.38,2580 4147.38,2270
GND_IN on Top Layer "GND_IN_L01_P036" (solid, remove dead copper, pour order 36): 3245,2605
AC1 on Top Layer "AC1_L01_P004" (solid, remove dead copper, pour order 4): 2445,2600 2275,2600 2275,2975 2445,2975
NetJ4_1 on Top Layer "NETJ4_1_L01_P002" (solid, remove dead copper, pour order 2): 2275,2150.49 2275,2560 2445,2560 2445,2150.49
AC2 on Top Layer "AC2_L01_P000" (solid, remove dead copper, pour order 0): 2055,2150 2055,2975 2235,2975 2235,2150
GND on Bottom Layer "GND_L02_P146" (solid, remove dead copper, pour order 146): 3405.49,3560 3405.49,2125 5469,2125 5460,2134 5460,3560
GND_IN on Bottom Layer "GND_IN_L02_P142" (solid, remove dead copper, pour order 142): 3254.51,2125 2485,2125 2485,3607.61 2947.01,3607.61 2947.01,3340 3280,3340
AC2 on Bottom Layer "AC2_L02_P110" (solid, pour order 110): 2235,4660 2235,4025 2115,4025 2115,4660
AC2 on Bottom Layer "AC2_L02_P108" (solid, remove dead copper, pour order 108): 2250,5945 2500,5945 2500,5630 2235,5630 2235,4810 2055,4810 2055,5825 2250,5825
AC1 on Bottom Layer "AC1_L02_P010" (solid, remove dead copper, pour order 10): 2445,2600 2445,2975 2445,3755 2445,3925 2275,3925 2275,2850 2275,2600
AC2 on Bottom Layer "AC2_L02_P008" (solid, remove dead copper, pour order 8): 2055,2600 2055,4825 2500,4825 2500,4510 2235,4510 2235,2600
AC2 on Bottom Layer "AC2_L02_P006" (solid, remove dead copper, pour order 6): 2055,2650

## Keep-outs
Keep-Out Layer:
  lines w10: 2025,2125 2025,6050 4560,6050 5015,6050 5015,4005 5469,3551 5469,3540 5469,2746 5469,2125 4575,2125 2025,2125 ; 3280,2230 3380,2230 3380,3340 3355,3340 3305,3340 3280,3340 3280,2317.64 3280,2230

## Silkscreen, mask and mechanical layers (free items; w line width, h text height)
Top Overlay:
  drawing of 1343 lines, arcs and shapes, not listed
  text "CN1_O/F" at 3515,5967.13 h30
  text "Channel 1" at 2115,5845 h30 r270
  text "CN1_ADC" at 3540,5730 h30
  text "CN2_PWM" at 3745,5725 h30
  text "Channel 2" at 2115,4780 h30 r270
  text "CN2_O/F" at 3615,4650 h30
  text "PROJECT 2" at 4418.12,4550 h40
  text "CN2_PWM" at 3715,4505 h30
  text "CN2_ADC" at 3520,4490 h30
  text "@Ven @Dung" at 4378.12,4435 h40
  text "Slave" at 4550,4190 h60
  text "5V" at 3859.57,3452.5 h30
  text "GND" at 3727.38,3450.42 h30
  text "RST" at 4705,2540 h30
  text "SWIM" at 4794,2540 h30
  text "SDA" at 5145,2540 h30
  text "SCL" at 5245,2540 h30
  text "+" at 5362,2535 h30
